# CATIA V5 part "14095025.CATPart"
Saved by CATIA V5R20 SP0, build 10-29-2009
Part number: 14095025
Definition: NONE
Nomenclature: 14095025
Source: Unknown
Description: 14095025
Bounding box of the stored display mesh (mm): x -12.5 to 50, y -61.5 to 51.6, z -51.6 to 51.6
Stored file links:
  C:\Users\Utente\Desktop\IO LAVORO\3D X SITO CF\X SITO\PLASTICA\RF2\14095025.CATPart
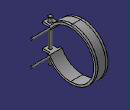
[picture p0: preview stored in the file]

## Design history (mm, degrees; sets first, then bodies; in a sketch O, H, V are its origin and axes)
Body1 "14095025" (main body)
  Solid1: solid without history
